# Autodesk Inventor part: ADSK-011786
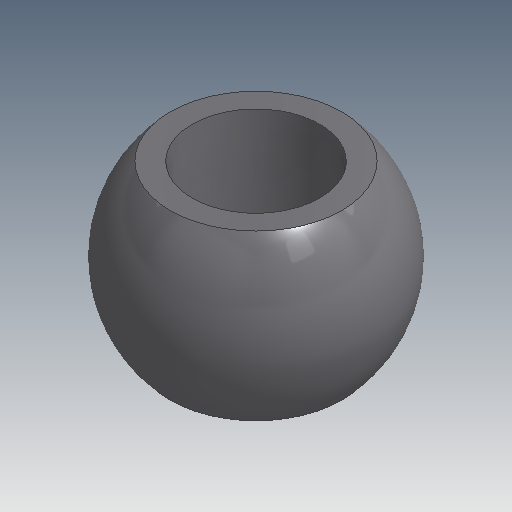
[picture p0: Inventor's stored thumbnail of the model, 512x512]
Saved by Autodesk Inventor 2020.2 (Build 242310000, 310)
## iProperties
Created: 1999-12
Part Number: ADSK-011786
Material: Acier (alliage faible hypertrempé)
Document SubType Name: Modeling
Designer: gpurviance
Density: 7.84 g/cm^3
Appearance: Metal-Steel(Polish)
Mass: 20.6192 g
Surface Area: 15.795 cm^2
Volume: 2.63 cm^3
Control State: 0
Master: False
Checked Out: False
Shininess: 0.0
Length Units: 11272
Angle Units: 11279
Time Units: 11290
Mass Units: 11286
Length Display Precision: 3
Angle Display Precision: 2
Compacted: True
Dimensions: 0,6x0,8x0,8 in
Mass: 0,045 lb
VLT_Material: Acier (alliage faible hypertrempé)
Density: 0.0
Volumn: 0.0
Area: 0.0
PropertySet Name: Model Information
Author: gpurviance
Revision Number: -
Title: ADSK-011786
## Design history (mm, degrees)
node "Revolution1" dims "d6" = 90 deg
node "Solide1"
node "Corps solides"
node "Corps surfaciques"
sketch "Sketch1"
  geometry: L1 (0, 14.287)-(0, -15.875) reference; L2 (0, -0.794)-(12.7, -0.794) reference; L3 (5.556, 6.35)-(7.446, 6.35); L4 (5.556, -7.938)-(7.446, -7.938); L5 (5.556, 6.35)-(5.556, -7.938); A1 r 10.319 centre (0, -0.794) between (7.446, -7.938) and (7.446, 6.35)
  constraints: 10 end point, 2 perpendicular, 2 point on circle, 2 vertical, 1 centre point, 1 coincident, 1 horizontal, 1 parallel
  dimensions: "d1" = 14.2875 distance between parallel lines of L4 L3; "d3" = 7.14375 distance between parallel lines of L2 L4 (= 0.5 x d1); "d4" = 5.55625 distance between parallel lines of L5 L1; "d5" = 10.31875 radius of A1
